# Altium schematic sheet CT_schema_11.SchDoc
size 382 x 278 mm
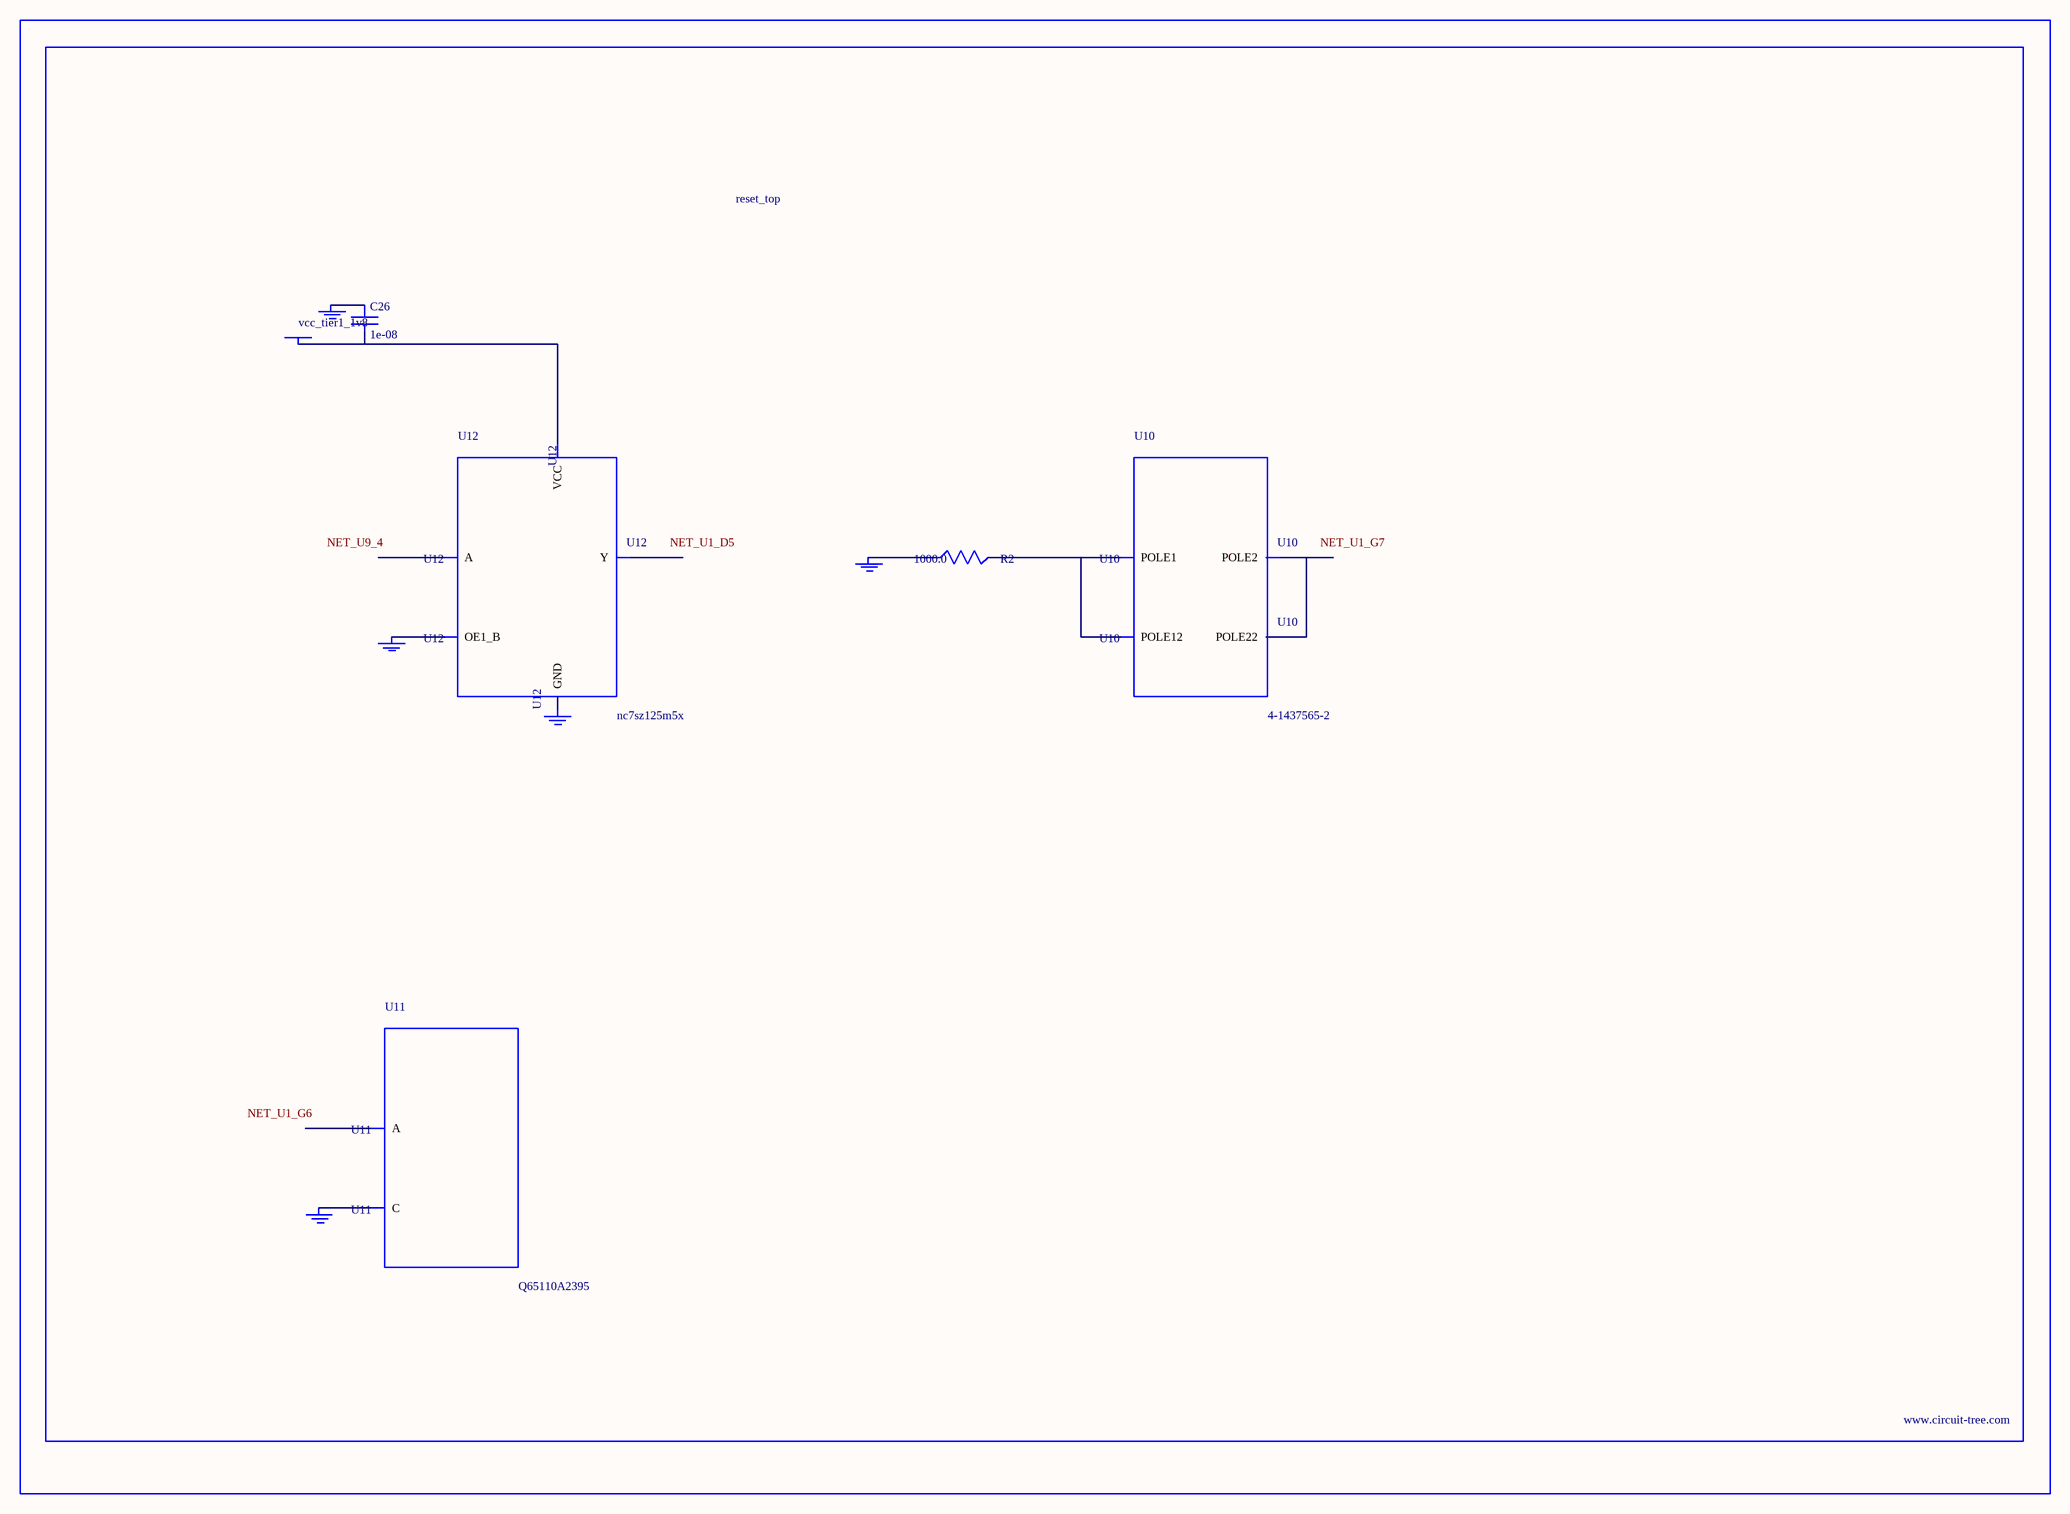
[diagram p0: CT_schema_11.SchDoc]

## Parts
BORDER10  (no value)
C26  1e-08  [C0402]
GND_INSTANCE_10_0  (no value)
GND_INSTANCE_10_1  (no value)
GND_INSTANCE_10_2  (no value)
GND_INSTANCE_10_3  (no value)
GND_INSTANCE_10_4  (no value)
POWER_INSTANCE_10_0  vcc_tier1_1v8
R2  1000.0  [R0603]
U10  4-1437565-2  [SW_4-1437565-2]
U11  Q65110A2395  [LGM67K-G1J2-24-Z]
U12  nc7sz125m5x  [NC7SZ125M5X]

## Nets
NetC26_1: C26.1 GND_INSTANCE_10_2.0(GND)
NetC26_2: C26.2 POWER_INSTANCE_10_0.0(PWR) U12.5(VCC)
NetGND_INSTANCE_10_0_0: GND_INSTANCE_10_0.0(GND) R2.1
NetGND_INSTANCE_10_1_0: GND_INSTANCE_10_1.0(GND) U11.C
NetGND_INSTANCE_10_3_0: GND_INSTANCE_10_3.0(GND) U12.1(OE1_B)
NetGND_INSTANCE_10_4_0: GND_INSTANCE_10_4.0(GND) U12.3(GND)
NetR2_2: R2.2 U10.1(POLE1) U10.2(POLE12)
NetU10_3: U10.3(POLE2) U10.4(POLE22)

Not connected (* = marked no-connect by the designer): U11 A; U12 2(A) 4(Y)

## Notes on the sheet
- Labels drawn without touching a wire or pin: NET_U1_D5, NET_U1_G6, NET_U1_G7, NET_U9_4

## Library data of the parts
BORDER10 = BORDER_PAGE10
C26 = C0402C103K3RAC
GND_INSTANCE_10_0-GND_INSTANCE_10_4 = GND
POWER_INSTANCE_10_0 = PWR
R2 = RC0603JR-071KL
